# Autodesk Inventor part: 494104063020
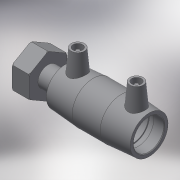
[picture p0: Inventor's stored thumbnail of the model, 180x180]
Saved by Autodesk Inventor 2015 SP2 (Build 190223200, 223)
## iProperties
Created: 2017-06
Part Number: 494104063020
Material: Generic
Description: PLASSON FEMALE FREE NUT TRANSITION COUPLER 63-2''
Document SubType Name: Modeling
Designer: KIM
Mass: 55.0731 g
Surface Area: 148.067 cm^2
Volume: 55.0731 cm^3
Density: 1 g/cm^3
Appearance: Default
Author: KIM
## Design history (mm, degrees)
derived "494104.ipt"
feature "Solid1::494104.ipt"
tag "TaggingFeature1"
body "Solid1"
other parameters: "d0" = 117, "d1" = 63, "d2" = 82, "d3" = 57, "d4" = 39, "d5" = 73.8, "d6" = 59.85, "d7" = 63, "d8" = 168 deg, "d10" = 22.8, "d11" = 7.6, "d29" = 57, "d30" = 14, "d31" = 40.95, "d34" = 5 deg, "d41" = 4, "d42" = 14, "d43" = 0, "d48" = 3, "d49" = 0, "d55" = 44, "d57" = 38, "d80" = 1.26, "d83" = 22, "d84" = 14.52, "d85" = 1.452, "d86" = 45.3248, "d87" = 56.656, "d88" = 84.984, "d89" = 82, "d90" = 1.69968, "d94" = 0, "d95" = 1.452, "d96" = 39.6592, "d_" = 63, "L_" = 161, "L_1" = 57, "D_1" = 82, "A_" = 57, "d_2" = 12, "L_2" = 44, "D_" = 38, "G_" = 56.656
